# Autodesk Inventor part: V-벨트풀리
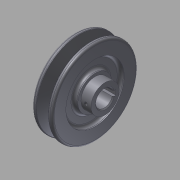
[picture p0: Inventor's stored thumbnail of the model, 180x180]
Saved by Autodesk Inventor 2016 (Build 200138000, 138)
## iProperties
Company: 한국ATC센터
Created: 2014-07
Part Number: V-벨트풀리
Document SubType Name: Modeling
Designer: KYOUNG IL JANG
Density: 7.87 g/cm^3
Material: 강철, 탄소
Mass: 593.766 g
Surface Area: 234.121 cm^2
Volume: 75.4468 cm^3
Appearance: 강철
Author: KYOUNG IL JANG
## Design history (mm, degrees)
sketch "스케치1"
  geometry: L1 (-15, 0)-(15, 0); L2 (-15, 0)-(-15, 17); L3 (-15, 17)-(-11, 17); L4 (-11, 17)-(-11, 29); L5 (-11, 29)-(-15, 29); L6 (-15, 29)-(-15, 42.5); L7 (-15, 42.5)-(-10.976, 42.5); L8 (-10.976, 42.5)-(-7.154, 30); L9 (-7.154, 30)-(-2.846, 30); L10 (-2.846, 30)-(0.976, 42.5); L11 (0.976, 42.5)-(5, 42.5); L12 (5, 42.5)-(5, 29); L13 (5, 29)-(1, 29); L14 (1, 29)-(1, 17); L15 (1, 17)-(5, 17); L16 (5, 17)-(5, 14); L17 (5, 14)-(15, 14); L18 (15, 14)-(15, 0); L19 (-9.6, 38)-(-0.4, 38); 2 further points
  constraints: 38 end point, 11 parallel, 7 collinear, 3 equal length, 3 perpendicular, 2 point on line, 1 coincident, 1 horizontal, 1 midpoint
  dimensions: "d0" = 30 distance of L1.start L1.end; "d1" = 4.5 distance between parallel lines of L7 L19; "d2" = 8 distance between parallel lines of L9 L19; "d3" = 9.2 distance of L19.start L19.end; "d4" = 34 deg angle of L10 L8; "d5" = 20 distance between parallel lines of L12 L6; "d6" = 76 diameter of L19 L1; "d7" = 4 distance of L2.end L3.end; "d8" = 34 diameter of L3 L1; "d9" = 58 diameter of L5 L1; "d10" = 28 diameter of L17 L1
revolve "회전1" sketch "스케치1" stored, may be unused: angle "d11" = 90 deg
sketch "스케치2"
  geometry: L1 (-2.5, 8.124)-(-2.5, 10.8); L2 (-2.5, 10.8)-(2.5, 10.8); L3 (2.5, 10.8)-(2.5, 8.124); A1 r 8.5 centre (0, 0) between (-2.5, 8.124) and (2.5, 8.124); 1 further point
  constraints: 6 end point, 2 parallel, 2 point on circle, 1 centre point, 1 coincident, 1 horizontal, 1 vertical
  dimensions: "d12" = 17 diameter of A1; "d13" = 5 distance of L1.end L2.end; "d14" = 19.3 dimension on A1 L2 (computed from d12)
extrude "돌출1" cut sketch "스케치2" stored distance "d15" = 10; taper "d16" = 0 deg
chamfer "모따기1" distance "d17" = 1; stored, may be unused: second distance "d18" = 2, angle "d19" = 45 deg
node "작업 평면1"
sketch "스케치3"
  geometry: L1 (5, -14)-(5, 14) reference; 3 further points
  constraints: 1 horizontal alignment, 1 midpoint
  dimensions: "d20" = 5 distance from line of L1 point (0, 0)
hole "구멍1" sketch "스케치3" at (0, 0) diameter "d21" = 3.242; stored, may be unused: countersink angle "d25" = 90 deg, drill point angle "d27" = 118 deg; dims "d22" = 6, "d23" = 4, "d24" = 2, "d26" = 8
fillet "모깎기1" dims "d28" = 3, "d29" = 2, "d30" = 0.5, "d31" = 1
node "솔리드1"
